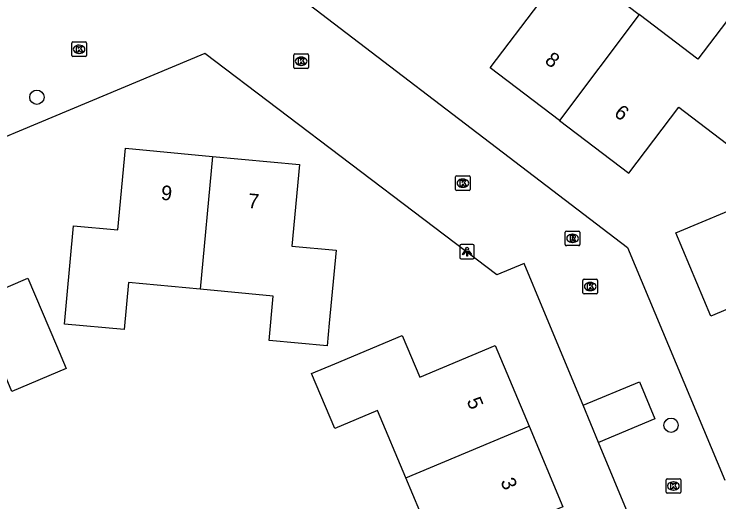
# Model space of a CAD drawing. Extents: x 158474 to 159560, y 388525 to 389605.
# Drawn here: x 158655.08 to 158703.27, y 389027.79 to 389061.16 of the extents above; entities that cross this region are included whole.
import ezdxf

# ---------------------------------------------------------------- set-up
doc = ezdxf.new("R2010")
doc.units = 0
for name, color, linetype in [('IMGEO_Boom', 7, 'Continuous'), ('IMGEO_Kolk', 7, 'Continuous'), ('IMGEO_Lichtpunt', 7, 'Continuous'), ('IMGEO_Pand', 7, 'Continuous'), ('IMGEO_Pand_nummerreeks', 7, 'Continuous'), ('IMGEO_Rijbaan_lokaal_open', 7, 'Continuous'), ('IMGEO_Rioolput', 7, 'Continuous')]:
    doc.layers.add(name, color=color, linetype=linetype)

msp = doc.modelspace()

# ---------------------------------------------------------------- linework, layer by layer
at = {"layer": 'IMGEO_Boom'}
for centre in [(158656.635, 389055.476), (158699.999, 389033.04)]:
    msp.add_circle(centre, 0.489, dxfattribs=at)
at = {"layer": 'IMGEO_Kolk'}
for p, q in [((158659.023, 389058.329), (158659.023, 389059.181)), ((158659.098, 389059.255), (158659.95, 389059.255)), ((158659.511, 389059.035), (158659.536, 389059.035)), ((158660.024, 389059.181), (158660.024, 389058.329)), ((158659.534, 389058.475), (158659.509, 389058.475)), ((158674.282, 389058.436), (158675.134, 389058.436)), ((158659.95, 389058.255), (158659.098, 389058.255)), ((158674.207, 389057.51), (158674.207, 389058.362)), ((158674.695, 389058.216), (158674.72, 389058.216)), ((158675.208, 389058.362), (158675.208, 389057.51)), ((158674.718, 389057.656), (158674.693, 389057.656)), ((158675.134, 389057.436), (158674.282, 389057.436)), ((158685.267, 389049.168), (158685.267, 389050.02)), ((158685.342, 389050.094), (158686.194, 389050.094)), ((158685.755, 389049.874), (158685.78, 389049.874)), ((158686.268, 389050.02), (158686.268, 389049.168)), ((158685.778, 389049.314), (158685.753, 389049.314)), ((158686.194, 389049.094), (158685.342, 389049.094)), ((158694.05, 389043.024), (158694.902, 389043.024)), ((158693.975, 389042.098), (158693.975, 389042.95)), ((158694.463, 389042.804), (158694.488, 389042.804)), ((158694.976, 389042.95), (158694.976, 389042.098)), ((158694.902, 389042.024), (158694.05, 389042.024)), ((158694.486, 389042.244), (158694.461, 389042.244)), ((158699.66, 389028.456), (158699.66, 389029.308)), ((158699.735, 389029.382), (158700.587, 389029.382)), ((158700.148, 389029.162), (158700.173, 389029.162)), ((158700.661, 389029.308), (158700.661, 389028.456)), ((158700.171, 389028.602), (158700.146, 389028.602)), ((158700.587, 389028.382), (158699.735, 389028.382))]:
    msp.add_line(p, q, dxfattribs=at)
for points in [[(158659.023, 389058.329), (158659.023, 389059.181)], [(158659.098, 389059.255), (158659.95, 389059.255)], [(158659.344, 389058.955), (158659.467, 389058.955), (158659.467, 389058.804), (158659.597, 389058.955), (158659.761, 389058.955), (158659.615, 389058.804), (158659.768, 389058.555), (158659.616, 389058.555), (158659.531, 389058.719), (158659.467, 389058.652), (158659.467, 389058.555), (158659.344, 389058.555), (158659.344, 389058.955)], [(158660.024, 389059.181), (158660.024, 389058.329)], [(158674.282, 389058.436), (158675.134, 389058.436)], [(158659.95, 389058.255), (158659.098, 389058.255)], [(158674.207, 389057.51), (158674.207, 389058.362)], [(158674.528, 389058.136), (158674.651, 389058.136), (158674.651, 389057.985), (158674.781, 389058.136), (158674.945, 389058.136), (158674.799, 389057.985), (158674.952, 389057.736), (158674.8, 389057.736), (158674.715, 389057.9), (158674.651, 389057.833), (158674.651, 389057.736), (158674.528, 389057.736), (158674.528, 389058.136)], [(158675.208, 389058.362), (158675.208, 389057.51)], [(158675.134, 389057.436), (158674.282, 389057.436)], [(158685.267, 389049.168), (158685.267, 389050.02)], [(158685.342, 389050.094), (158686.194, 389050.094)], [(158685.588, 389049.794), (158685.711, 389049.794), (158685.711, 389049.643), (158685.841, 389049.794), (158686.005, 389049.794), (158685.859, 389049.643), (158686.012, 389049.394), (158685.86, 389049.394), (158685.775, 389049.558), (158685.711, 389049.491), (158685.711, 389049.394), (158685.588, 389049.394), (158685.588, 389049.794)], [(158686.268, 389050.02), (158686.268, 389049.168)], [(158686.194, 389049.094), (158685.342, 389049.094)], [(158694.05, 389043.024), (158694.902, 389043.024)], [(158693.975, 389042.098), (158693.975, 389042.95)], [(158694.296, 389042.724), (158694.419, 389042.724), (158694.419, 389042.573), (158694.549, 389042.724), (158694.713, 389042.724), (158694.567, 389042.573), (158694.72, 389042.324), (158694.568, 389042.324), (158694.483, 389042.488), (158694.419, 389042.421), (158694.419, 389042.324), (158694.296, 389042.324), (158694.296, 389042.724)], [(158694.976, 389042.95), (158694.976, 389042.098)], [(158694.902, 389042.024), (158694.05, 389042.024)], [(158699.66, 389028.456), (158699.66, 389029.308)], [(158699.735, 389029.382), (158700.587, 389029.382)], [(158699.981, 389029.082), (158700.104, 389029.082), (158700.104, 389028.931), (158700.234, 389029.082), (158700.398, 389029.082), (158700.252, 389028.931), (158700.405, 389028.682), (158700.253, 389028.682), (158700.168, 389028.846), (158700.104, 389028.779), (158700.104, 389028.682), (158699.981, 389028.682), (158699.981, 389029.082)], [(158700.661, 389029.308), (158700.661, 389028.456)], [(158700.587, 389028.382), (158699.735, 389028.382)]]:
    msp.add_lwpolyline(points, dxfattribs=at)
for centre, start, end in [((158659.1, 389059.179), 91.552, 178.448), ((158659.1, 389059.179), 91.552, 178.448), ((158659.948, 389059.179), 1.552, 88.448), ((158659.948, 389059.179), 1.552, 88.448), ((158674.284, 389058.36), 91.552, 178.448), ((158674.284, 389058.36), 91.552, 178.448), ((158675.132, 389058.36), 1.552, 88.448), ((158675.132, 389058.36), 1.552, 88.448), ((158659.1, 389058.331), 181.552, 268.448), ((158659.1, 389058.331), 181.552, 268.448), ((158659.948, 389058.331), 271.552, 358.448), ((158659.948, 389058.331), 271.552, 358.448), ((158674.284, 389057.512), 181.552, 268.448), ((158674.284, 389057.512), 181.552, 268.448), ((158675.132, 389057.512), 271.552, 358.448), ((158675.132, 389057.512), 271.552, 358.448), ((158685.344, 389050.018), 91.552, 178.448), ((158685.344, 389050.018), 91.552, 178.448), ((158686.192, 389050.018), 1.552, 88.448), ((158686.192, 389050.018), 1.552, 88.448), ((158685.344, 389049.17), 181.552, 268.448), ((158685.344, 389049.17), 181.552, 268.448), ((158686.192, 389049.17), 271.552, 358.448), ((158686.192, 389049.17), 271.552, 358.448), ((158694.052, 389042.948), 91.552, 178.448), ((158694.052, 389042.948), 91.552, 178.448), ((158694.9, 389042.948), 1.552, 88.448), ((158694.9, 389042.948), 1.552, 88.448), ((158694.052, 389042.1), 181.552, 268.448), ((158694.052, 389042.1), 181.552, 268.448), ((158694.9, 389042.1), 271.552, 358.448), ((158694.9, 389042.1), 271.552, 358.448), ((158699.737, 389029.306), 91.552, 178.448), ((158699.737, 389029.306), 91.552, 178.448), ((158700.585, 389029.306), 1.552, 88.448), ((158700.585, 389029.306), 1.552, 88.448), ((158699.737, 389028.458), 181.552, 268.448), ((158699.737, 389028.458), 181.552, 268.448), ((158700.585, 389028.458), 271.552, 358.448), ((158700.585, 389028.458), 271.552, 358.448)]:
    msp.add_arc(centre, 0.0765, start, end, dxfattribs=at)
for centre, major_axis, ratio, start_param, end_param in [((158659.51, 389058.755), (-0.387, 0.002), 0.722429, 4.712389, 7.853982), ((158659.535, 389058.755), (-0.39, 0.002), 0.717154, 1.570796, 4.712389), ((158674.694, 389057.936), (-0.387, 0.002), 0.722429, 4.712389, 7.853982), ((158674.719, 389057.936), (-0.39, 0.002), 0.717154, 1.570796, 4.712389), ((158685.754, 389049.594), (-0.387, 0.002), 0.722429, 4.712389, 7.853982), ((158685.779, 389049.594), (-0.39, 0.002), 0.717154, 1.570796, 4.712389), ((158694.462, 389042.524), (-0.387, 0.002), 0.722429, 4.712389, 7.853982), ((158694.487, 389042.524), (-0.39, 0.002), 0.717154, 1.570796, 4.712389), ((158700.147, 389028.882), (-0.387, 0.002), 0.722429, 4.712389, 7.853982), ((158700.172, 389028.882), (-0.39, 0.002), 0.717154, 1.570796, 4.712389)]:
    msp.add_ellipse(centre, major_axis=major_axis, ratio=ratio, start_param=start_param, end_param=end_param, dxfattribs=at)
at = {"layer": 'IMGEO_Lichtpunt'}
for p, q in [((158686.452, 389045.411), (158685.644, 389045.411)), ((158686.452, 389045.411), (158685.644, 389045.411)), ((158685.55, 389045.316), (158685.55, 389044.509)), ((158685.55, 389045.316), (158685.55, 389044.509)), ((158686.546, 389044.509), (158686.546, 389045.316)), ((158686.546, 389044.509), (158686.546, 389045.316)), ((158685.644, 389044.415), (158686.452, 389044.415)), ((158685.644, 389044.415), (158686.452, 389044.415))]:
    msp.add_line(p, q, dxfattribs=at)
for points in [[(158685.924, 389044.98), (158685.963, 389044.952), (158685.775, 389044.69), (158685.737, 389044.717), (158685.924, 389044.98)], [(158686.026, 389044.932), (158686.073, 389044.932), (158686.073, 389044.61), (158686.026, 389044.61), (158686.026, 389044.932)], [(158686.136, 389044.952), (158686.174, 389044.979), (158686.361, 389044.717), (158686.322, 389044.689), (158686.136, 389044.952)]]:
    msp.add_lwpolyline(points, dxfattribs=at)
msp.add_circle((158686.049, 389045.114), 0.0994, dxfattribs=at)
for centre, start, end in [((158685.644, 389045.316), 90, 180), ((158685.644, 389045.316), 90, 180), ((158686.452, 389045.316), 0, 90), ((158686.452, 389045.316), 0, 90), ((158685.644, 389044.509), 180, 270), ((158685.644, 389044.509), 180, 270), ((158686.452, 389044.509), 270, 0), ((158686.452, 389044.509), 270, 360)]:
    msp.add_arc(centre, 0.0946, start, end, dxfattribs=at)
at = {"layer": 'IMGEO_Pand'}
for points in [[(158692.61, 389069.18), (158695.844, 389066.719), (158693.885, 389064.144), (158697.825, 389061.145)], [(158692.361, 389053.889), (158687.621, 389057.497), (158691.015, 389061.956), (158688.544, 389063.837)], [(158697.825, 389061.145), (158692.361, 389053.889)], [(158709.319, 389056.434), (158703.785, 389060.645), (158701.84, 389058.089), (158697.825, 389061.145)], [(158709.319, 389056.434), (158712.035, 389049.984), (158713.989, 389045.224), (158711.088, 389044.008), (158707.33, 389042.433), (158702.718, 389040.5), (158700.329, 389046.199), (158705.458, 389048.349), (158703.8, 389052.306)], [(158692.361, 389053.889), (158697.101, 389050.282), (158700.533, 389054.791), (158703.8, 389052.306)], [(158667.798, 389042.337), (158662.904, 389042.792), (158662.606, 389039.583), (158658.522, 389039.963), (158658.684, 389041.698), (158659.147, 389046.676), (158662.176, 389046.394), (158662.695, 389051.981), (158668.642, 389051.428)], [(158668.642, 389051.428), (158674.589, 389050.875), (158674.068, 389045.284), (158677.089, 389045.003), (158676.626, 389040.025), (158676.481, 389038.46), (158672.517, 389038.829), (158672.8, 389041.871), (158667.798, 389042.337)], [(158668.642, 389051.428), (158667.798, 389042.337)], [(158645.458, 389044.717), (158651.013, 389047.058), (158653.187, 389041.9), (158656.024, 389043.096), (158657.966, 389038.489), (158658.632, 389036.91), (158654.922, 389035.347), (158653.67, 389038.316), (158648.988, 389036.342)], [(158681.863, 389029.433), (158679.929, 389034.043), (158677.002, 389032.816), (158675.424, 389036.578), (158677.014, 389037.245), (158681.624, 389039.178), (158682.824, 389036.319), (158687.982, 389038.482), (158690.294, 389032.972)], [(158681.863, 389029.433), (158690.294, 389032.972)], [(158690.294, 389032.972), (158692.605, 389027.462), (158687.417, 389025.286), (158688.586, 389022.499)], [(158682.383, 389019.972), (158682.014, 389020.851), (158680.844, 389023.642), (158683.776, 389024.872), (158681.863, 389029.433)]]:
    msp.add_lwpolyline(points, dxfattribs=at)
at = {"layer": 'IMGEO_Rijbaan_lokaal_open'}
for points in [[(158668.409, 389067.056), (158697.03, 389045.201), (158703.674, 389029.291)], [(158693.979, 389034.415), (158691.297, 389040.872), (158689.958, 389044.098), (158688.082, 389043.319), (158668.118, 389058.458), (158641.722, 389047.425), (158602.187, 389030.899), (158601.851, 389031.612), (158596.34, 389029.317)], [(158693.979, 389034.415), (158697.841, 389036.019), (158698.899, 389033.47), (158695.038, 389031.866)], [(158695.038, 389031.866), (158693.979, 389034.415)], [(158701.755, 389009.057), (158702.875, 389012.992), (158695.038, 389031.866)]]:
    msp.add_lwpolyline(points, dxfattribs=at)
at = {"layer": 'IMGEO_Rioolput'}
for p, q in [((158692.765, 389045.396), (158692.765, 389046.248)), ((158692.84, 389046.322), (158693.692, 389046.322)), ((158693.253, 389046.102), (158693.278, 389046.102)), ((158693.766, 389046.248), (158693.766, 389045.396)), ((158693.276, 389045.542), (158693.251, 389045.542)), ((158693.692, 389045.322), (158692.84, 389045.322))]:
    msp.add_line(p, q, dxfattribs=at)
for points in [[(158692.765, 389045.396), (158692.765, 389046.248)], [(158692.84, 389046.322), (158693.692, 389046.322)], [(158693.354, 389046.02), (158693.102, 389046.022), (158693.102, 389045.622)], [(158693.28, 389045.941), (158693.226, 389045.941), (158693.226, 389045.86)], [(158693.766, 389046.248), (158693.766, 389045.396)], [(158693.102, 389045.622), (158693.226, 389045.622), (158693.226, 389045.784), (158693.237, 389045.784)], [(158693.226, 389045.86), (158693.278, 389045.86)], [(158693.284, 389045.755), (158693.355, 389045.622), (158693.495, 389045.622), (158693.43, 389045.748)], [(158693.692, 389045.322), (158692.84, 389045.322)]]:
    msp.add_lwpolyline(points, dxfattribs=at)
for centre, radius, start, end in [((158692.842, 389046.246), 0.0765, 91.552, 178.448), ((158692.842, 389046.246), 0.0765, 91.552, 178.448), ((158693.286, 389045.845), 0.0964, 77.0061, 93.1865), ((158693.3, 389045.902), 0.0378, 276.6634, 79.6772), ((158693.353, 389045.91), 0.109, 350.3612, 89.416), ((158693.351, 389045.91), 0.112, 277.5842, 350.9817), ((158693.69, 389046.246), 0.0765, 1.552, 88.448), ((158693.69, 389046.246), 0.0765, 1.552, 88.448), ((158692.842, 389045.398), 0.0765, 181.552, 268.448), ((158692.842, 389045.398), 0.0765, 181.552, 268.448), ((158693.236, 389045.731), 0.0533, 26.0293, 88.6989), ((158693.262, 389046.049), 0.19, 274.7715, 282.9687), ((158693.335, 389045.695), 0.108, 29.5134, 73.7905), ((158693.69, 389045.398), 0.0765, 271.552, 358.448), ((158693.69, 389045.398), 0.0765, 271.552, 358.448)]:
    msp.add_arc(centre, radius, start, end, dxfattribs=at)
for centre, major_axis, ratio, start_param, end_param in [((158693.252, 389045.822), (-0.387, 0.002), 0.722429, 4.712389, 7.853982), ((158693.277, 389045.822), (-0.39, 0.002), 0.717154, 1.570796, 4.712389)]:
    msp.add_ellipse(centre, major_axis=major_axis, ratio=ratio, start_param=start_param, end_param=end_param, dxfattribs=at)

# ---------------------------------------------------------------- texts
at = {"layer": 'IMGEO_Pand_nummerreeks'}
for s, rotation, p in [('8', 322.7261, (158691.301, 389057.863)), ('6', 322.7261, (158696.038, 389054.257)), ('9', 354.6875, (158665.091, 389048.464)), ('7', 354.6875, (158671.038, 389047.911)), ('5', 292.7416, (158686.005, 389034.712)), ('3', 292.7755, (158688.318, 389029.2))]:
    msp.add_text(s, height=1, rotation=rotation, dxfattribs=at).set_placement(p)

doc.saveas('drawing.dxf')
